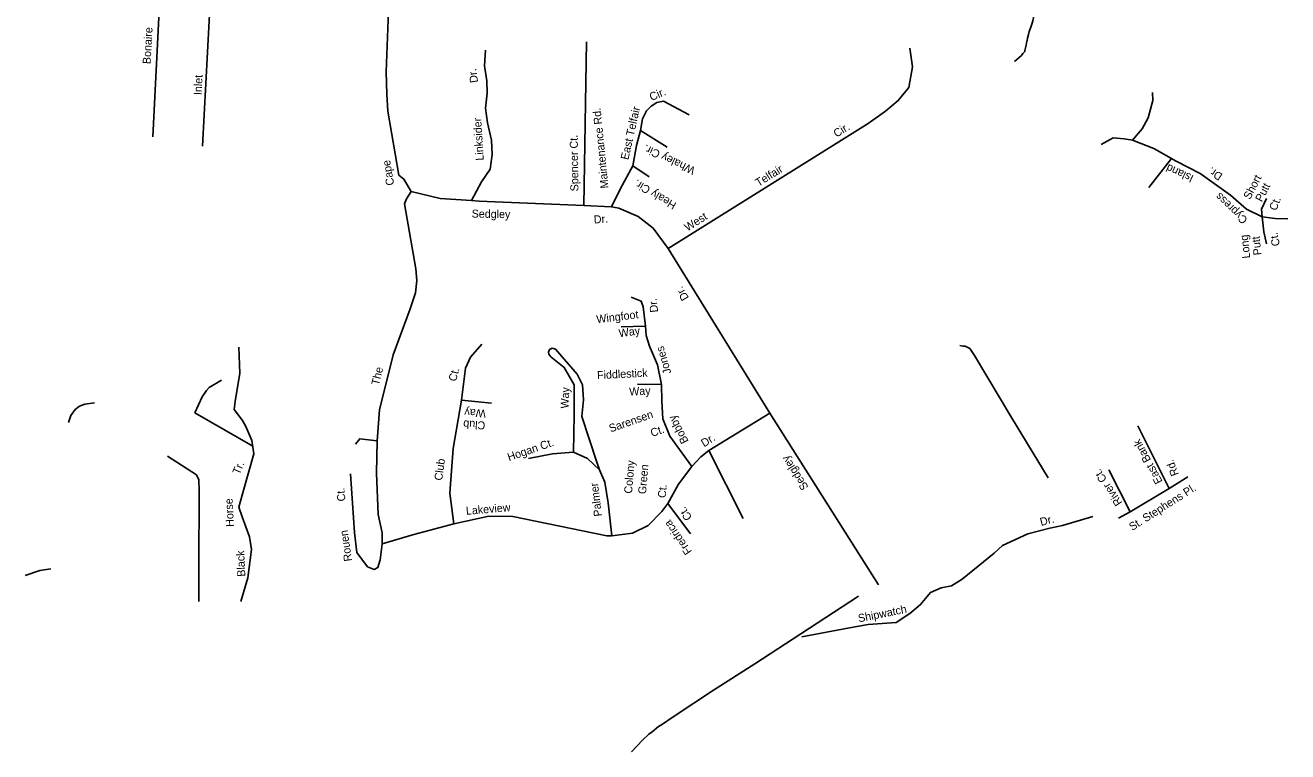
# Model space of a CAD drawing. Extents: x 2308163 to 2335412, y -96774 to 127732.
# Drawn here: x 2321528 to 2324116, y -15796 to -14306 of the extents above; entities that cross this region are included whole.
import ezdxf

# ---------------------------------------------------------------- set-up
doc = ezdxf.new("R2010")
doc.units = 0
doc.layers.add('Old_Level_10', color=7, linetype='Continuous')
doc.layers.add('Old_Level_35', color=7, linetype='Continuous')

msp = doc.modelspace()

# ---------------------------------------------------------------- linework, layer by layer
at = {"layer": 'Old_Level_35'}
for points in [[(2321789.3, -14534.3), (2321836.4, -13595), (2321826.4, -13512.2)], [(2321891.4, -14553.6), (2321908, -14231.6), (2321917.3, -14120.1), (2321917.7, -14004.7), (2321927.3, -13885.9), (2321918.3, -13771.9), (2321919.1, -13696.8), (2321937.8, -13633.3), (2321945.2, -13576.8), (2321946.3, -13494.3)], [(2322319, -14646.7), (2322304.2, -14621.1), (2322294, -14613.4), (2322271.3, -14481.7), (2322269.3, -14447.1), (2322267.8, -14400.9), (2322271.5, -14294.2), (2322270.3, -14267), (2322266.3, -14199.8), (2322262, -14143.1), (2322264.1, -14112.8), (2322275.6, -14082.9), (2322299.8, -14051.2), (2322317.6, -14020.4), (2322333.7, -13978), (2322353.1, -13901.2), (2322372.6, -13822.3), (2322399.2, -13720.6), (2322421.4, -13622.9), (2322429, -13567.8)], [(2323581.8, -14336.6), (2323583, -14332.3), (2323584.7, -14324.9), (2323586.3, -14318.4), (2323589.5, -14309.5), (2323592.3, -14301.1), (2323593.9, -14296.5), (2323594.4, -14293.1), (2323595, -14290.1), (2323594.6, -14285.6), (2323595.2, -14280.6), (2323593.2, -14261), (2323590, -14227.9), (2323585.9, -14190.8), (2323584.2, -14178.3), (2323584.1, -14161.8), (2323583.6, -14142.3), (2323584.8, -14109.8), (2323586.5, -14058.8), (2323589.8, -13986.4), (2323591.7, -13935.3)], [(2322672.9, -14675), (2322678.4, -14339.5)], [(2323555.8, -14379.7), (2323570.1, -14367.6), (2323573.2, -14363.6), (2323575.7, -14360.7), (2323577.3, -14359.3), (2323577.4, -14357.2), (2323579.7, -14346.3), (2323581.3, -14338.3), (2323581.8, -14336.6)], [(2322471.4, -14356.6), (2322469.2, -14389), (2322474.4, -14419.6), (2322474.6, -14444.7), (2322471.4, -14476), (2322475.7, -14505.5), (2322483.9, -14541.4), (2322484.9, -14570.7), (2322480.7, -14601), (2322463.1, -14626.5), (2322442.9, -14665)], [(2322845.9, -14763.7), (2323256.1, -14507.1), (2323291.6, -14482.1), (2323317.5, -14460), (2323339.4, -14433.5), (2323347.1, -14390.8), (2323341.1, -14352.9)], [(2323797.7, -14541), (2323817.6, -14518.3), (2323830.1, -14495.4), (2323839.8, -14459.7), (2323839.3, -14443.8)], [(2322729.4, -14678), (2322748.5, -14640.4), (2322773.2, -14594.1), (2322780.9, -14552.5), (2322789.3, -14521.3), (2322793.3, -14497.4), (2322801.2, -14480.9), (2322810.9, -14471.8), (2322822.7, -14463.8), (2322836.4, -14461.2), (2322888.9, -14489.2)], [(2322789.3, -14521.3), (2322843.6, -14555.7)], [(2323733.7, -14550.5), (2323758.6, -14536.5), (2323780.9, -14538.3), (2323797.7, -14541), (2323841.7, -14558.4), (2323887.5, -14584.4), (2323936.6, -14609.4), (2323998.7, -14654), (2324031.7, -14682.7), (2324064.1, -14698.7), (2324062.5, -14682.7), (2324072.8, -14660.8)], [(2322773.2, -14594.1), (2322807, -14616.2)], [(2323831.5, -14638.7), (2323877.6, -14578.8)], [(2322319, -14646.7), (2322309.1, -14661.9), (2322305.6, -14672.2), (2322328.3, -14804.9), (2322330.6, -14829.1), (2322327.6, -14854.1), (2322317, -14887.3), (2322282.3, -14981.4), (2322254.3, -15094.4), (2322249, -15158.1), (2322247.8, -15224), (2322251.1, -15308.9), (2322259.3, -15346.9), (2322259.6, -15368.9), (2322255.3, -15402.3), (2322250.5, -15417.8), (2322243.1, -15421.8), (2322229.6, -15416.1), (2322207.6, -15387), (2322202.7, -15346), (2322194.3, -15225.3)], [(2322894.4, -15210.9), (2322912.9, -15190.6), (2322929.1, -15177.5), (2323054.3, -15101.2), (2322845.9, -14763.7), (2322814.9, -14721.8), (2322784.3, -14697.7), (2322745, -14680.7), (2322729.4, -14678), (2322672.9, -14675), (2322458.6, -14666.6), (2322442.9, -14665), (2322378.1, -14660.7), (2322319, -14646.7)], [(2324064.1, -14698.7), (2324067.3, -14729.6), (2324072.8, -14754.2)], [(2324064.1, -14698.7), (2324090.5, -14701.7), (2324116.3, -14702.8)], [(2322259.6, -15368.9), (2322324.1, -15350.2), (2322406.6, -15327.9), (2322478.4, -15312.6), (2322527.7, -15313.2), (2322670.2, -15342.4), (2322720.2, -15352.5), (2322730.6, -15352.9), (2322772.8, -15347), (2322804.7, -15331.4), (2322833, -15303), (2322845.1, -15286.7), (2322867, -15246.6), (2322894.4, -15210.9), (2322849.4, -15148.6), (2322834.9, -15112.5), (2322833, -15076.8), (2322832.1, -15042.2), (2322824.1, -15002.2), (2322807.6, -14963.9), (2322801, -14941.7), (2322799.5, -14922.8), (2322794.6, -14882.8), (2322790.8, -14871.2), (2322770.2, -14863.1)], [(2322799.5, -14922.8), (2322749.2, -14924.2)], [(2322406.6, -15327.9), (2322398.5, -15265.4), (2322404.8, -15173.5), (2322421.9, -15074.6), (2322430.4, -15008.9), (2322440.6, -14986.2), (2322463.6, -14959.8)], [(2321969.7, -15487.6), (2321984.3, -15439.1), (2321991.8, -15380.8), (2321987.2, -15354.9), (2321972.1, -15314.1), (2321965.5, -15293.7), (2321975.9, -15257.4), (2321996.7, -15184.8), (2321992.2, -15157.2), (2321979.9, -15128.3), (2321973.4, -15116.2), (2321955.8, -15093.6), (2321958.2, -15077.2), (2321967.6, -15018.9), (2321965.8, -14965.6)], [(2322651.9, -15181), (2322653.5, -15104.6), (2322653.5, -15042.8), (2322632.7, -15007.5), (2322605.2, -14985.6), (2322601.2, -14980.2), (2322600.3, -14976), (2322602.5, -14970.9), (2322607.9, -14967.9), (2322615.1, -14970.2), (2322659.5, -15021), (2322670.3, -15043.4), (2322672.4, -15073.8), (2322669.1, -15108.2), (2322699.4, -15201.4), (2322705.1, -15217.4)], [(2323624.8, -15233.8), (2323550.2, -15109.9), (2323473.7, -14983.1), (2323464.6, -14968.3), (2323460.6, -14966.2), (2323455.2, -14964.1), (2323450.2, -14963.5), (2323443.7, -14962.3)], [(2321875.4, -15100.3), (2321890.6, -15068), (2321899.4, -15054.9), (2321904.6, -15048.4), (2321929.9, -15033.5)], [(2322832.1, -15042.2), (2322782.9, -15041.6)], [(2321616.6, -15120.6), (2321621.2, -15106.1), (2321630.1, -15093.7), (2321639.2, -15087.1), (2321650, -15082.5), (2321669.5, -15080)], [(2322421.9, -15074.6), (2322483.5, -15080.9)], [(2321875.4, -15100.3), (2321994.1, -15168.8)], [(2323054.3, -15101.2), (2323276.9, -15453.2)], [(2323808.7, -15127.2), (2323873.3, -15255.7), (2323911.3, -15231.5)], [(2322249, -15158.1), (2322213.5, -15153.7), (2322204.8, -15164.9)], [(2321819.2, -15189.2), (2321878.8, -15227.5), (2321883.5, -15237.9), (2321884.4, -15260), (2321883.9, -15419.9), (2321883.8, -15487.4)], [(2322730.6, -15352.9), (2322722.7, -15285), (2322715.8, -15242.9), (2322705.1, -15217.4), (2322680.8, -15194.5), (2322651.9, -15181), (2322608.8, -15184.7), (2322559.2, -15194.5)], [(2322929.1, -15177.5), (2322999.7, -15317.2)], [(2323793.1, -15303.8), (2323749.4, -15217.4)], [(2323873.3, -15255.7), (2323793.1, -15303.8), (2323769.3, -15316.8)], [(2322845.1, -15286.7), (2322891.7, -15349)], [(2323120.1, -15559.6), (2323217.5, -15541.8), (2323256, -15534.6), (2323313.5, -15530.2), (2323341.7, -15512.1), (2323363.6, -15493.8), (2323383.5, -15469), (2323405.5, -15459.1), (2323426.9, -15455.6), (2323448.6, -15441.5), (2323514.1, -15388.6), (2323531.7, -15372.3), (2323583.5, -15348.6), (2323628.4, -15337.4), (2323654.1, -15331.9), (2323716.3, -15312.8)], [(2321527.7, -15434.1), (2321557.3, -15423.7), (2321580.2, -15420.7)], [(2323236.4, -15476.6), (2323118, -15553.9), (2323023.5, -15615.1), (2322939.1, -15669.6), (2322856.3, -15724.1), (2322831.9, -15740.1), (2322826.3, -15743.5), (2322813, -15754.6), (2322806.3, -15759.5), (2322793, -15772.1), (2322770.8, -15795.6)]]:
    msp.add_lwpolyline(points, dxfattribs=at)

# ---------------------------------------------------------------- texts
at = {"layer": 'Old_Level_10'}
for s, height, rotation, p in [('Bonaire', 16.4, 86.8529, (2321784.6, -14385.6)), ('Inlet', 16.4, 87.8162, (2321889.6, -14449.1)), ('Dr.', 16.4, 98.3115, (2322456.3, -14422.5)), ('Cir.', 16.4, 22.8854, (2322811.6, -14461.2)), ('Linksider', 16.4, 93.4684, (2322467.8, -14582.7)), ('Maintenance Rd.', 16.404, 95.7048, (2322723.7, -14639.5)), ('East Telfair ', 16.404, 77.2768, (2322764.1, -14582.7)), ('Cir.', 16.4, 31.7692, (2323191.1, -14536.3)), ('Spencer Ct.', 16.404, 90.7324, (2322661.9, -14646.2)), ('Whaley Cir.', 16.404, 154.835, (2322902.8, -14598)), ('Cape', 16.4, 99.9628, (2322284.4, -14632.8)), ('Telfair', 16.4, 31.8069, (2323031.1, -14637.1)), (' Island ', 16.4, 155.2034, (2323930.3, -14616.6)), ('Dr.', 16.4, 146.8638, (2323984.1, -14611.6)), ('Healy Cir.', 16.4, 149.1209, (2322864.4, -14670.5)), ('Short', 16.4, 62.5056, (2324038.9, -14664.3)), ('Cypress', 16.4, 136.1992, (2324035.4, -14703.3)), ('Putt', 16.4, 62.5056, (2324063.1, -14669.2)), ('Ct.', 16.4, 68.6681, (2324092.7, -14687.2)), ('Sedgley', 16.4, 358.9794, (2322442.9, -14700)), ('Dr.', 16.4, 3.7721, (2322693.9, -14712.3)), ('West', 16.4, 32.3643, (2322885.5, -14728.8)), ('Long', 16.4, 95.9768, (2324039.4, -14783.1)), ('Putt', 16.4, 95.9768, (2324062.6, -14776.5)), ('Ct.', 16.4, 101.7692, (2324100.5, -14756.9)), ('Dr.', 16.4, 121.0201, (2322888.9, -14864.5)), ('Dr.', 16.4, 96.5311, (2322825.4, -14893.8)), ('Wingfoot ', 16.4, 6.8876, (2322699.7, -14916.8)), ('Way', 16.4, 8.3091, (2322745.8, -14945.7)), ('Jones', 16.4, 106.3222, (2322852.4, -15018.5)), ('The ', 16.4, 76.327, (2322252.9, -15045.2)), ('Ct.', 16.4, 75.0685, (2322410.8, -15037.3)), ('Fiddlestick', 16.404, 2.8383, (2322700.5, -15031.5)), ('Way', 16.4, 87.7119, (2322641.6, -15092)), ('Way', 16.4, 2.8383, (2322766.4, -15065.2)), ('Way', 16.4, 176.6967, (2322472.4, -15094.1)), ('Club', 16.4, 176.6967, (2322471.3, -15118.5)), ('Sarensen', 16.4, 19.2289, (2322727.9, -15140.9)), ('Bobby', 16.4, 117.1145, (2322888.1, -15158.8)), ('Ct.', 16.4, 19.2289, (2322812.9, -15150.1)), ('Hogan Ct.', 16.4, 19.0033, (2322519.6, -15199.8)), ('Dr.', 16.4, 32.3018, (2322919.7, -15171.4)), ('East Bank', 16.4, 118.3259, (2323860.1, -15241.2)), ('Club ', 16.4, 82.3139, (2322382.4, -15240.2)), ('Sedgley', 16.4, 122.9112, (2323134.3, -15252.7)), ('Tr.', 16.4, 66.8835, (2321966.9, -15228.6)), ('Colony', 16.4, 85.3278, (2322771.7, -15266.7)), ('Green ', 16.4, 85.3278, (2322800.4, -15267.7)), ('River Ct.', 16.4, 123.4059, (2323777.9, -15284.9)), ('Rd.', 16.4, 110.7645, (2323893.2, -15226.6)), ('Palmer', 16.4, 97.0173, (2322710.3, -15312.1)), ('Ct.', 16.4, 94.6733, (2322184.2, -15281.5)), ('Ct.', 16.4, 85.3278, (2322840.9, -15275.6)), ('St. Stephens Pl.', 16.404, 32.4762, (2323797.3, -15343)), ('Horse', 16.4, 92.966, (2321955.7, -15334)), ('Lakeview', 16.4, 4.7502, (2322431.9, -15309.8)), ('Ct.', 16.4, 124.4823, (2322895.8, -15314.7)), ('Fredrica', 16.4, 124.4823, (2322895.4, -15384.8)), ('Dr.', 16.4, 14.4843, (2323610.5, -15332.6)), ('Rouen', 16.4, 98.3217, (2322197.8, -15404.1)), ('Black', 16.4, 92.67, (2321979, -15436.2)), ('Shipwatch', 16.4, 11.3903, (2323237, -15530.3))]:
    msp.add_text(s, height=height, rotation=rotation, dxfattribs=at).set_placement(p)

doc.saveas('drawing.dxf')
